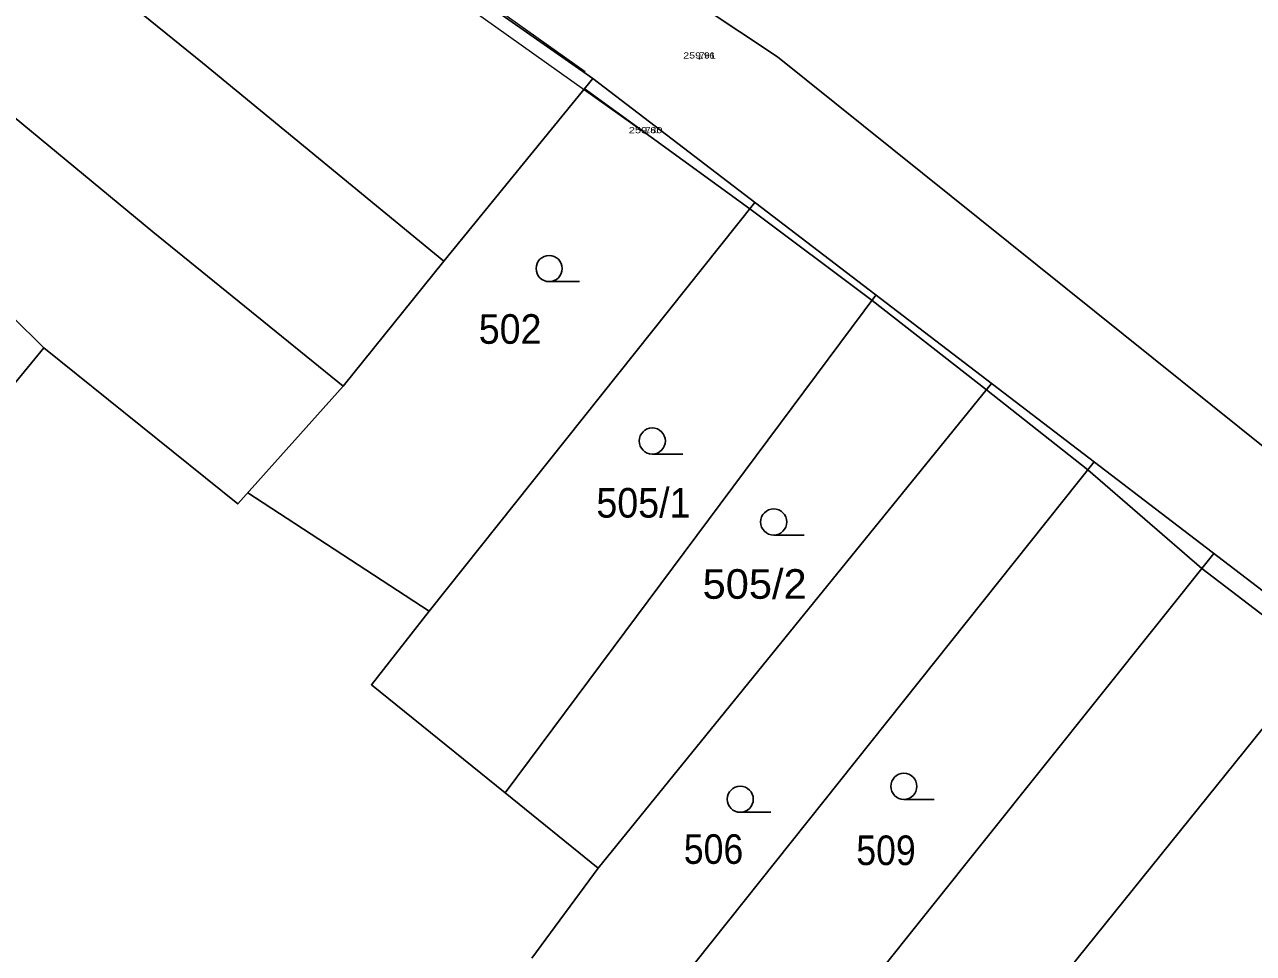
# Model space of a CAD drawing. Extents: x -568530 to -568223, y -1154101 to -1153740.
# Drawn here: x -568398.2 to -568327.6, y -1154028.8 to -1153975.4 of the extents above; entities that cross this region are included whole.
import ezdxf
from ezdxf.enums import TextEntityAlignment as Align

# ---------------------------------------------------------------- set-up
doc = ezdxf.new("R2010")
doc.units = 0
doc.header["$LTSCALE"] = 0.14
doc.header["$PDMODE"] = 32
doc.header["$PDSIZE"] = 0.07
for name, color, linetype, lineweight in [('1', 7, 'Continuous', 25), ('11', 7, 'Continuous', 13), ('12', 7, 'Continuous', 13), ('25', 7, 'Continuous', 13), ('4', 7, 'Continuous', 25), ('52', 7, 'Continuous', 13), ('7', 7, 'Continuous', 13)]:
    doc.layers.add(name, color=color, linetype=linetype, lineweight=lineweight)
doc.layers.add('13', color=7, linetype='Continuous')
doc.layers.add('18', color=7, linetype='Continuous')

msp = doc.modelspace()

# ---------------------------------------------------------------- linework, layer by layer
at = {"layer": '1'}
for p, q in [((-568408.2, -1153972.93), (-568390.78, -1153987.34)), ((-568356.23, -1153985.65), (-568374.92, -1154009.12)), ((-568370.56, -1154019.54), (-568349.28, -1153990.97)), ((-568342.64, -1153996.04), (-568365.23, -1154023.86)), ((-568336.76, -1154000.54), (-568364.47, -1154035.32)), ((-568374.92, -1154009.12), (-568385.34, -1154002.31)), ((-568329.89, -1154005.8), (-568355.84, -1154038.27)), ((-568350.83, -1154045.34), (-568323.15, -1154010.95)), ((-568365.23, -1154023.86), (-568370.56, -1154019.54)), ((-568365.23, -1154023.86), (-568369.04, -1154029.03))]:
    msp.add_line(p, q, dxfattribs=at)
for points in [[(-568414.4, -1153956.01), (-568407.59, -1153961.72), (-568387.94, -1153977.62)], [(-568381.21, -1153967.57), (-568365.54, -1153978.53), (-568303.79, -1154025.76)], [(-568365.54, -1153978.53), (-568374.09, -1153989.01), (-568387.94, -1153977.62)], [(-568374.09, -1153989.01), (-568379.87, -1153996.2), (-568390.78, -1153987.34)], [(-568426.69, -1153995.54), (-568409.36, -1154009.01), (-568397.04, -1153994), (-568400.7, -1153990.39)], [(-568379.87, -1153996.2), (-568385.91, -1154002.95), (-568397.04, -1153994)], [(-568370.56, -1154019.54), (-568378.24, -1154013.34), (-568374.92, -1154009.12)]]:
    msp.add_lwpolyline(points, dxfattribs=at)
at = {"layer": '11'}
for p in [(-568359.41, -1153977.38), (-568362.5, -1153981.67)]:
    msp.add_point(p, dxfattribs=at)
at = {"layer": '25', "lineweight": 25}
for p, q in [((-568368.04, -1153990.19), (-568366.29, -1153990.19)), ((-568362.12, -1154000.09), (-568360.37, -1154000.09)), ((-568355.15, -1154004.74), (-568353.4, -1154004.74)), ((-568347.68, -1154019.92), (-568345.93, -1154019.92)), ((-568357.07, -1154020.66), (-568355.32, -1154020.66))]:
    msp.add_line(p, q, dxfattribs=at)
for centre in [(-568368.04, -1153989.44), (-568362.12, -1153999.34), (-568355.15, -1154003.99), (-568347.68, -1154019.17), (-568357.07, -1154019.91)]:
    msp.add_circle(centre, 0.75, dxfattribs=at)
at = {"layer": '4'}
for points in [[(-568416.35, -1153942.92), (-568411.96, -1153940.51), (-568386.96, -1153956.01), (-568354.94, -1153977.29), (-568293.66, -1154026.45)], [(-568366.02, -1153979.11), (-568356.52, -1153986.02), (-568349.5, -1153991.27), (-568342.94, -1153996.41), (-568337.12, -1154000.99), (-568330.58, -1154006.67), (-568323.84, -1154011.81), (-568317.63, -1154016.68)]]:
    msp.add_lwpolyline(points, dxfattribs=at)
at = {"layer": '52'}
msp.add_lwpolyline([(-568440.61, -1153926.76), (-568414.88, -1153944.05), (-568397.12, -1153956.51), (-568380.33, -1153967.93), (-568365.972, -1153978.132)], dxfattribs=at)
at = {"layer": '7'}
msp.add_lwpolyline([(-568397.3, -1153957.22), (-568391.53, -1153961.19), (-568377.5, -1153970.99), (-568362.5, -1153981.67)], dxfattribs=at)

# ---------------------------------------------------------------- texts
at = {"layer": '12'}
for s, width, p in [('259.91', 1.3, (-568359.41, -1153977.38)), ('259.80', 1.35, (-568362.4995, -1153981.67))]:
    msp.add_text(s, height=0.35, dxfattribs=dict(at, width=width)).set_placement(p, align=Align.CENTER)
at = {"layer": '13'}
for s, width, p in [('766', 1.1, (-568359.41, -1153977.38)), ('767', 1.05, (-568362.5, -1153981.67))]:
    msp.add_text(s, height=0.35, dxfattribs=dict(at, width=width)).set_placement(p)
at = {"layer": '18'}
for s, width, p in [('502', 0.95, (-568372.08, -1153993.76)), ('505/1', 0.95, (-568365.33, -1154003.74)), ('505/2', 1.05, (-568359.23, -1154008.4)), ('506', 0.9, (-568360.31, -1154023.62)), ('509', 0.9, (-568350.41, -1154023.69))]:
    msp.add_text(s, height=1.7, dxfattribs=dict(at, width=width)).set_placement(p)

doc.saveas('drawing.dxf')
